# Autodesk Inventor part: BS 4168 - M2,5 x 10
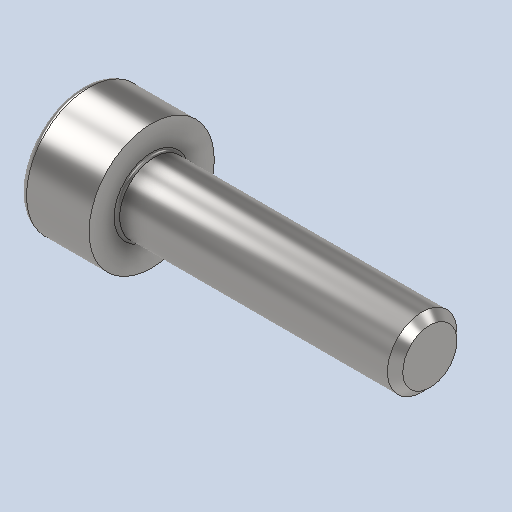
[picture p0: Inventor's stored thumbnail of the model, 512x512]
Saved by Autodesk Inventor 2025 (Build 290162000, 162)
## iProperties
Created: 2024-01
Part Number: BS 4168 - M2,5 x 10
Material: Acciaio, Dolce
Description: Vite con esagono incassato
Document SubType Name: Modeling
Designer: Ryzen5700u
Density: 7.85 g/cm^3
Appearance: Default
Author: Ryzen5700u
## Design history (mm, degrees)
feature "Solid1"
node "Solido1"
